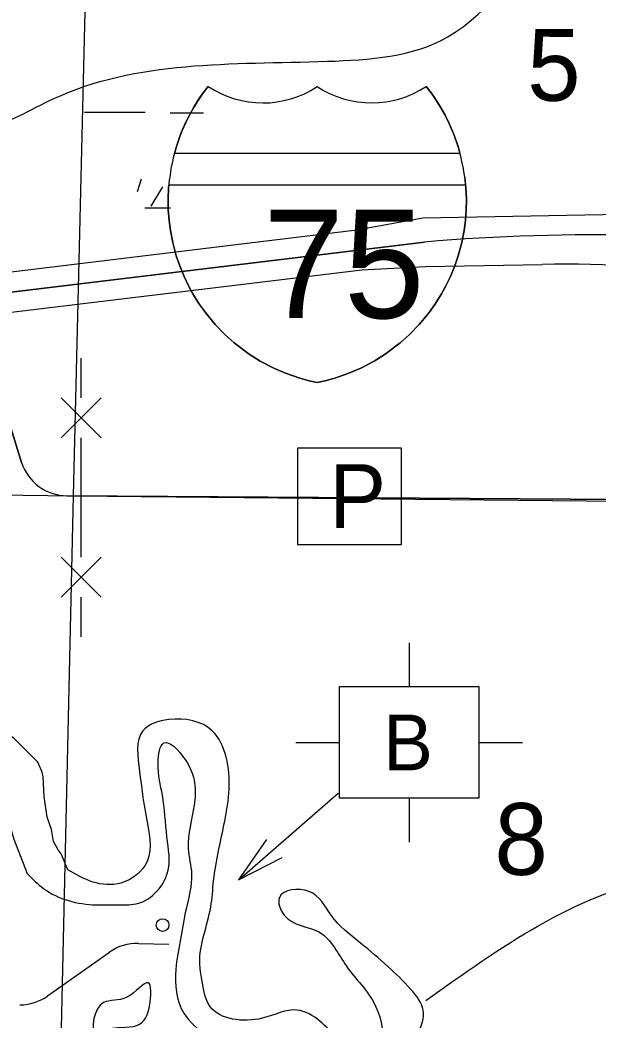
# Model space of a CAD drawing. Extents: x 408847 to 817539, y 923858 to 1151780.
# Drawn here: x 546759 to 550386, y 1005294 to 1011568 of the extents above; entities that cross this region are included whole.
import ezdxf

# ---------------------------------------------------------------- set-up
doc = ezdxf.new("R2010")
doc.units = 0
for name, color, linetype in [('Culture', 7, 'Continuous'), ('Interstate Divided Highway Outline and Fill', 7, 'Continuous'), ('Lakes and Ponds', 7, 'Continuous'), ('Level 4', 7, 'Continuous'), ('Level 43', 7, 'Continuous'), ('Local Roads Paved', 7, 'Continuous'), ('Local Roads Related Cells', 7, 'Continuous'), ('Local Roads Related Text', 7, 'Continuous'), ('Narrow River Creek and Branch and Slough', 7, 'Continuous'), ('Roadshields Interstates', 7, 'Continuous'), ('Section Lines', 7, 'Continuous'), ('Swamps', 7, 'Continuous')]:
    doc.layers.add(name, color=color, linetype=linetype)

msp = doc.modelspace()

# ---------------------------------------------------------------- linework, layer by layer
at = {"layer": 'Culture'}
for p, q in [((549201.2, 1007661.4), (549201.2, 1007386.4)), ((548489.7, 1007035.7), (548764.7, 1007035.7)), ((549637.7, 1007035.7), (549912.7, 1007035.7)), ((548135.6, 1006178.2), (548755.3, 1006717.5)), ((549201.2, 1006685.1), (549201.2, 1006410.1)), ((548306.5, 1006427.2), (548129.5, 1006173.7)), ((548129.5, 1006173.7), (548405, 1006314.1))]:
    msp.add_line(p, q, dxfattribs=at)
msp.add_lwpolyline([(548764.7, 1007386.4), (549637.7, 1007386.4), (549637.7, 1006685.1), (548764.7, 1006685.1)], close=True, dxfattribs=at)
msp.add_circle((547653.3, 1005889.8), 39.9, dxfattribs=at)
at = {"layer": 'Interstate Divided Highway Outline and Fill'}
for p, q in [((551016.8, 1010355.7), (549286.1, 1010325.9)), ((549286.1, 1010325.9), (548871.8, 1010249.9)), ((548871.8, 1010249.9), (545795.3, 1009877.4)), ((548903.4, 1010001.9), (549304, 1010022.6)), ((549304, 1010022.6), (550036.9, 1010035.1)), ((545825.3, 1009629.3), (548903.4, 1010001.9))]:
    msp.add_line(p, q, dxfattribs=at)
msp.add_arc((550180.9, 1001636.3), 8400, 82.73539, 90.98248, dxfattribs=at)
at = {"layer": 'Lakes and Ponds'}
for points in [[(547058.1, 1006236.9), (547017.7, 1006336.7), (546997.9, 1006361.4), (546968.2, 1006413.5), (546955.8, 1006490.3), (546930.1, 1006567.3), (546910.3, 1006696.2), (546903.8, 1006819.9), (546898.9, 1006849.6), (546871.6, 1006911.5), (546720.6, 1007062.7), (546574.5, 1007156.9), (546470.8, 1007191.8)], [(545884.7, 1007078), (546091.7, 1007028), (546256.6, 1007020.8), (546464.6, 1006953.9), (546598.3, 1006812.6), (546647.8, 1006671.4), (546675.8, 1006579.4), (546720.4, 1006428.3), (546805, 1006212.6)]]:
    msp.add_lwpolyline(points, dxfattribs=at)
for points in [[(548245.3, 1005041.2), (548347.5, 1005124.9), (548511.4, 1005144.3), (548732.8, 1005043.4), (548976.2, 1004928.4), (549132.4, 1005027.8), (549257, 1005209.5), (549289.6, 1005355.5), (549210.2, 1005487.9), (549066.9, 1005630.6), (548897.6, 1005775.3), (548710.5, 1005952.2), (548571.2, 1006100.8), (548387.2, 1006063.5), (548416.7, 1005951.3), (548638.1, 1005844.4), (548807.1, 1005631.6), (548990, 1005380.7), (549001, 1005136.4), (548853, 1005121), (548641.9, 1005285.9), (548498.3, 1005356.5), (548278.3, 1005305.3), (547950.9, 1005380.6), (547900, 1005547.4), (547887.1, 1005650.6), (547955.9, 1006003.2), (547974, 1006169.2), (548043.4, 1006541.2), (548053, 1006943.5), (547965.8, 1007107.9), (547692.3, 1007179), (547530.2, 1007109.6), (547509.1, 1006853.5), (547550, 1006571.1), (547556.8, 1006288.8), (547392.6, 1006153.7), (547216.6, 1006160), (547058.1, 1006236.9)], [(546805, 1006212.6), (546906.7, 1006119.2), (547236.7, 1006016.7), (547287.7, 1006016.7), (547379.5, 1006016.7), (547501.9, 1006026.9), (547684.4, 1006218.3), (547681.3, 1006442.5), (547652.4, 1006704.8), (547625.3, 1006907.1), (547661.7, 1007033), (547795.2, 1006928.5), (547852, 1006642), (547814.9, 1006369.9), (547835.5, 1006209.6), (547801.1, 1005990.3), (547766.7, 1005801.1), (547736.6, 1005611.9), (547786.8, 1005337.2), (547932.1, 1005194.5), (548013.8, 1005116.2), (548047.3, 1005018), (548042.5, 1004815.8), (547970.2, 1004728), (547777.1, 1004906.9), (547595.8, 1005035.7), (547442.3, 1005130.4)], [(547442.3, 1005130.4), (547330.8, 1005236.9), (547492.8, 1005260.3), (547571.2, 1005382.1), (547563.8, 1005528.2), (547429.5, 1005436.6), (547283.5, 1005403.2), (547229.2, 1005164.7), (547384, 1004984), (547564.6, 1004837.8), (547796.8, 1004640), (547960.2, 1004528.2), (548321.4, 1004425), (548519.2, 1004476.6), (548639.6, 1004701.5), (548900.8, 1004582.4), (548913.9, 1004342.1), (548838.7, 1004022.2), (548797.9, 1003836.2), (548968.7, 1003549.3), (549296.4, 1003556), (549566.1, 1003551), (549671.4, 1003396.5), (549656.4, 1003130.3), (549675.2, 1002834), (549800.1, 1002597.4), (550029.7, 1002532.4), (550272.9, 1002399.4), (550370.2, 1002232.9), (550245.6, 1002065.2), (550175.7, 1002075.5), (550077.7, 1002055.9), (549871.4, 1001926.6), (549640.9, 1001749.3), (549409.8, 1001431.9), (549323.1, 1001232.1), (549609.4, 1000878.7), (549737, 1000804.2), (550189.2, 1000718.5), (550434, 1000749.1), (550638, 1000820.5), (550892.9, 1000942.9), (551175.1, 1001139), (551391.1, 1001180.2), (551538.7, 1001121.6), (551554, 1000953.4), (551493.5, 1000807.5), (551398.5, 1000549.7), (551289.7, 1000311.9), (551196.7, 1000050), (551175.7, 999793.9), (551296.8, 999591.3), (551543.6, 999360.1), (551764.2, 999535.5), (551901.1, 999791.1), (552076, 999943.5), (552147.3, 999963.8), (552260.8, 999803.8), (552198.7, 999273.6), (552235.4, 998939.2), (552275.9, 998594.8), (552304.9, 998336.4), (552357.9, 998112.1), (552512.9, 997885.3), (552773.6, 997628.1), (552855, 997483.7), (552889.3, 997059.2), (552927.5, 996889), (553029.5, 996450.4), (553162.1, 996103.7), (553223.3, 995930.3), (553366.1, 995644.7), (553539.4, 995440.8), (553937.2, 995145), (554069.8, 994961.4), (554230.1, 994560.1), (554179.3, 994348.1), (554028.4, 994088.5), (553869.6, 993848.9), (553777.1, 993717.1), (553725.8, 993885.5), (553766.4, 994043.4), (553670.1, 993933.7), (553595.3, 993725.8), (553671.9, 993395.3), (553773, 993192.7), (554033.6, 992883.5), (554507.8, 992537.4), (554814.2, 992224), (555087.4, 992070.8), (555316.3, 991843.8), (555627.9, 991808.6), (555813.3, 991707.8), (555946.6, 991557.2), (556165.5, 991338.2), (556245.2, 991271.8), (556145.3, 991270.2)]]:
    msp.add_spline(points, degree=3, dxfattribs=at)
at = {"layer": 'Level 4'}
for p, q in [((545810.3, 1009753.3), (549296.8, 1010175.4)), ((549296.8, 1010175.4), (545810.3, 1009753.3))]:
    msp.add_line(p, q, dxfattribs=at)
msp.add_arc((550363.7, 997633.2), 12587.5, 69.85627, 94.86209, dxfattribs=at)
at = {"layer": 'Local Roads Paved'}
for p, q in [((547142.9, 1009197.6), (547142.9, 1009447.6)), ((546769.3, 1008793), (546630.1, 1009233.4)), ((546630.1, 1009233.4), (546769.3, 1008793)), ((547017.9, 1008947.6), (547267.9, 1009197.6)), ((547017.9, 1009197.6), (547267.9, 1008947.6)), ((547142.9, 1008197.6), (547142.9, 1008947.6)), ((550761.2, 1008558.5), (547053.3, 1008583.4)), ((547053.3, 1008583.4), (550761.2, 1008558.5)), ((547017.9, 1007947.6), (547267.9, 1008197.6)), ((547017.9, 1008197.6), (547267.9, 1007947.6)), ((547142.9, 1007697.6), (547142.9, 1007947.6)), ((547502.1, 1005775.2), (547692.6, 1005769.9)), ((547502.1, 1005775.2), (547692.6, 1005769.9)), ((546932.5, 1005444.9), (547320.2, 1005720)), ((546932.5, 1005444.9), (547320.2, 1005720))]:
    msp.add_line(p, q, dxfattribs=at)
for centre, start, end in [((547055.4, 1008883.4), 197.54619, 269.61455), ((547055.4, 1008883.4), 197.54619, 269.61455), ((547493.8, 1005475.3), 88.40506, 125.36111), ((547493.8, 1005475.3), 88.40506, 125.36111), ((546758.8, 1005689.5), 270.02985, 305.36116), ((546758.8, 1005689.5), 270.02985, 305.36116)]:
    msp.add_arc(centre, 300, start, end, dxfattribs=at)
at = {"layer": 'Local Roads Related Cells'}
for p, q in [((548499.7, 1008881.3), (548499.7, 1008278.1)), ((549152.9, 1008881.3), (548499.7, 1008881.3)), ((549152.9, 1008278.1), (549152.9, 1008881.3)), ((548499.7, 1008278.1), (549152.9, 1008278.1))]:
    msp.add_line(p, q, dxfattribs=at)
at = {"layer": 'Narrow River Creek and Branch and Slough'}
for points in [[(545555.9, 1010530.8), (546088, 1010809.6), (546534.3, 1010879.5), (546967.3, 1011073.6), (548686.4, 1011309.4), (549439.1, 1011459.9), (550200.1, 1012084.7), (550446.5, 1012163.6), (550943.1, 1012303.3), (551490.7, 1012636.9), (551914.1, 1013321.5), (552212.3, 1013770.5), (553294.1, 1014878.1)], [(546092.1, 1010817.8), (546355.6, 1011538.9), (546441.9, 1012421.3), (546551.7, 1013205.5), (546771.3, 1013544.7), (547297.7, 1014024.6), (547492.4, 1014183.8)], [(549305.2, 1005417.1), (550767.6, 1006182.6), (552213, 1006347.2), (552407.3, 1006460.5), (552521.9, 1006630.2), (552820.3, 1006801.3), (553242.8, 1007009.8), (553679, 1007140.3), (554142.9, 1007228.6), (554521, 1007329.2), (554917, 1007419.8), (555200.9, 1007464.7), (555452.8, 1007489.8), (555700.8, 1007534.9), (555861.5, 1007748.5), (555900.7, 1008066.6), (556015.4, 1008252.3), (556159.4, 1008291.8), (556315.5, 1008355.2)]]:
    msp.add_spline(points, degree=3, dxfattribs=at)
at = {"layer": 'Roadshields Interstates'}
for p, q in [((547728.3, 1010731.4), (547729.8, 1010736.8)), ((549519.6, 1010731.4), (547728.3, 1010731.4)), ((549549.6, 1010581.4), (549555.3, 1010531.4)), ((549555.3, 1010531.4), (547692.7, 1010531.4))]:
    msp.add_line(p, q, dxfattribs=at)
for points in [[(547939.8, 1011151.8), (547908.5, 1011110.6), (547888.1, 1011081.5), (547849.7, 1011021), (547821.5, 1010970.6), (547798.1, 1010923.6), (547768.7, 1010855.3), (547740.5, 1010775.2), (547720.8, 1010704.3), (547716, 1010681.4)], [(547729.8, 1010736.8), (547728.4, 1010731.4), (547740.5, 1010775.2), (547768.7, 1010855.3), (547798.1, 1010923.6), (547821.5, 1010970.6), (547849.7, 1011021), (547888.1, 1011081.5), (547908.5, 1011110.6), (547939.8, 1011151.8)], [(549532, 1010681.4), (549527.1, 1010704.3), (549507.5, 1010775.2), (549479.3, 1010855.3), (549449.9, 1010923.6), (549426.5, 1010970.6), (549398.2, 1011021), (549359.9, 1011081.5), (549339.5, 1011110.6), (549308.1, 1011151.8)], [(549308.1, 1011151.8), (549339.5, 1011110.6), (549359.9, 1011081.5), (549398.2, 1011021), (549426.5, 1010970.6), (549449.9, 1010923.6), (549479.3, 1010855.3), (549507.5, 1010775.2), (549519.6, 1010731.4)], [(547716, 1010681.4), (547706.4, 1010635.9), (547705.7, 1010631.4)], [(549542.2, 1010631.4), (549541.6, 1010635.9), (549532, 1010681.4)], [(547698.4, 1010581.4), (547695.8, 1010563.7), (547691.5, 1010519.7), (547688.2, 1010442.4), (547689.4, 1010377.1), (547694.4, 1010310.7), (547702.6, 1010248.6), (547717.3, 1010172.6), (547739.6, 1010089.7), (547761, 1010026.7), (547788.2, 1009960.1), (547819.4, 1009895.4), (547844.1, 1009850.5), (547886.3, 1009783.1), (547922.3, 1009732.7), (547983.3, 1009658.5), (548046.2, 1009593.6), (548103.7, 1009542.2), (548197.1, 1009471.9), (548266.3, 1009428.5), (548351, 1009384.1), (548424.8, 1009352.3), (548514, 1009321.6), (548573.5, 1009305.5), (548624, 1009294.4)], [(547705.7, 1010631.4), (547698.4, 1010581.4)], [(548624, 1009294.4), (548674.5, 1009305.5), (548734, 1009321.6), (548823.2, 1009352.3), (548896.9, 1009384.1), (548981.6, 1009428.5), (549050.8, 1009471.9), (549144.2, 1009542.2), (549201.7, 1009593.6), (549264.6, 1009658.5), (549325.7, 1009732.7), (549361.7, 1009783.1), (549403.9, 1009850.5), (549428.6, 1009895.4), (549459.8, 1009960.1), (549487, 1010026.7), (549508.4, 1010089.7), (549530.7, 1010172.6), (549545.4, 1010248.6), (549553.6, 1010310.7), (549558.6, 1010377.1), (549559.8, 1010442.4), (549556.4, 1010519.7), (549552.2, 1010563.7), (549549.6, 1010581.4)], [(548624, 1009294.4), (548674.5, 1009305.5), (548734, 1009321.6), (548823.2, 1009352.3), (548896.9, 1009384.1), (548981.6, 1009428.5), (549050.8, 1009471.9), (549144.2, 1009542.2), (549201.7, 1009593.6), (549264.6, 1009658.5), (549325.7, 1009732.7), (549361.7, 1009783.1), (549403.9, 1009850.5), (549428.6, 1009895.4), (549459.8, 1009960.1), (549487, 1010026.7), (549508.4, 1010089.7), (549530.7, 1010172.6), (549545.4, 1010248.6), (549553.6, 1010310.7), (549558.6, 1010377.1), (549559.8, 1010442.4), (549556.4, 1010519.7), (549552.2, 1010563.7), (549549.6, 1010581.4)], [(549549.6, 1010581.4), (549542.2, 1010631.4)], [(547692.7, 1010531.4), (547693, 1010532.7), (547691.5, 1010519.7), (547688.2, 1010442.4), (547689.4, 1010377.1), (547694.4, 1010310.7), (547702.6, 1010248.6), (547717.3, 1010172.6), (547739.6, 1010089.7), (547761, 1010026.7), (547788.2, 1009960.1), (547819.4, 1009895.4), (547844.1, 1009850.5), (547886.3, 1009783.1), (547922.3, 1009732.7), (547983.3, 1009658.5), (548046.2, 1009593.6), (548103.7, 1009542.2), (548197.1, 1009471.9), (548266.3, 1009428.5), (548351, 1009384.1), (548424.8, 1009352.3), (548514, 1009321.6), (548573.5, 1009305.5), (548624, 1009294.4)], [(548624, 1009294.4), (548573.5, 1009305.5), (548514, 1009321.6), (548424.8, 1009352.3), (548351, 1009384.1), (548266.3, 1009428.5), (548197.1, 1009471.9), (548103.7, 1009542.2), (548046.2, 1009593.6), (547983.3, 1009658.5), (547922.3, 1009732.7), (547886.3, 1009783.1), (547844.1, 1009850.5), (547819.4, 1009895.4), (547788.2, 1009960.1), (547761, 1010026.7), (547739.6, 1010089.7), (547717.3, 1010172.6), (547702.6, 1010248.6), (547694.4, 1010310.7), (547689.4, 1010377.1), (547688.2, 1010442.4), (547691.5, 1010519.7), (547692.7, 1010531.4)], [(549555.3, 1010531.4), (549556.4, 1010519.7), (549559.8, 1010442.4), (549558.6, 1010377.1), (549553.6, 1010310.7), (549545.4, 1010248.6), (549530.7, 1010172.6), (549508.4, 1010089.7), (549487, 1010026.7), (549459.8, 1009960.1), (549428.6, 1009895.4), (549403.9, 1009850.5), (549361.7, 1009783.1), (549325.7, 1009732.7), (549264.6, 1009658.5), (549201.7, 1009593.6), (549144.2, 1009542.2), (549050.8, 1009471.9), (548981.6, 1009428.5), (548896.9, 1009384.1), (548823.2, 1009352.3), (548734, 1009321.6), (548674.5, 1009305.5), (548624, 1009294.4)]]:
    msp.add_lwpolyline(points, dxfattribs=at)
for centre, radius, start, end in [((548833.3, 1010439), 1143, 141.41605, 165.17517), ((548282.9, 1011667.6), 619.4, 236.36906, 303.40952), ((548282.9, 1011667.6), 619.4, 236.36906, 303.40952), ((548282.9, 1011667.6), 619.4, 236.36906, 303.40952), ((548965.1, 1011672.3), 623.4, 236.82864, 303.39279), ((548965.1, 1011672.3), 623.4, 236.82864, 303.39279), ((548965.1, 1011672.3), 623.4, 236.82864, 303.39279)]:
    msp.add_arc(centre, radius, start, end, dxfattribs=at)
at = {"layer": 'Section Lines'}
for p, q in [((547220.3, 1013906.1), (547093.2, 1008582.5)), ((541695.4, 1008655.3), (547093.2, 1008582.5)), ((547093.2, 1008582.6), (546972.4, 1003254.5)), ((547093.2, 1008582.6), (552430.4, 1008529.8))]:
    msp.add_line(p, q, dxfattribs=at)
at = {"layer": 'Swamps'}
msp.add_line((547652.6, 1010522.1), (547580.1, 1010401.3), dxfattribs=at)
for points in [[(547164.4, 1010989.2), (547544.4, 1010989.2)], [(547700.2, 1010986.6), (547911, 1010986.6)], [(547519.7, 1010570.5), (547493.2, 1010490.9)], [(547542.8, 1010389.2), (547703.4, 1010389.2)]]:
    msp.add_lwpolyline(points, dxfattribs=at)

# ---------------------------------------------------------------- texts
at = {"layer": 'Culture'}
msp.add_text('B', height=350, dxfattribs=at).set_placement((549037.6, 1006860.7))
at = {"layer": 'Level 43'}
for s, p in [('5', (549941, 1011062.4)), ('8', (549735.4, 1006205.7))]:
    msp.add_text(s, height=450, rotation=359.72069, dxfattribs=at).set_placement(p)
at = {"layer": 'Local Roads Related Text'}
msp.add_text('P', height=400, dxfattribs=at).set_placement((548699.1, 1008381.4))
at = {"layer": 'Roadshields Interstates'}
msp.add_text('75', height=680, dxfattribs=at).set_placement((548286.2, 1009697.9))

doc.saveas('drawing.dxf')
